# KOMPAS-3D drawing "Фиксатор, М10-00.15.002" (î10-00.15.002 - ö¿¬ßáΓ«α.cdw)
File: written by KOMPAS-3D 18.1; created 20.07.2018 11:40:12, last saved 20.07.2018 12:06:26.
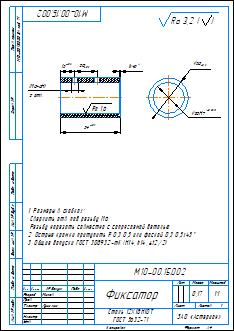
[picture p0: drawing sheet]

Sheet 1: A4, portrait

Document properties: Полное имя файла: D:\Magna\Магна Ins\Магна ins 10\М10-00.00.000\3Д\М10-00.15.002 - Фиксатор.cdw; Масса: 0.168272

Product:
- Part/product: Фиксатор  | designation М10-00.15.002
    Масса: 0.168272
    Раздел спецификации: Детали
    Форматы листов документа: A4
    source file: М10-00.15.002 - Фиксатор.cdw

Title block, sheet 1: Наименование: Фиксатор; designation: М10-00.15.002; Масса: 0,17; scale: 1:1; Количество листов документа: 1; organisation: ЗАО «Астерион»; Форматы листов документа: A4; stored path: Z:\Магна\Магна Ins\Магна ins 10\М10-00.00.000\3Д\М10-00.15.002 - Фиксатор.cdw; Разработал: Милов; Т. контр.: Лучихин

Views: Вид 1, Местный разрез 1, Вид:1, Проекционный вид 2
Referenced files in Z:\Магна\Магна Ins\Магна ins 10\М10-00.00.000\3Д\: М10-00.15.002 - Фиксатор.m3d
Referenced files in D:\Magna\Магна Ins\Магна ins 10\М10-00.00.000\3Д\: М10-00.15.002 - Фиксатор.m3d
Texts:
  Сталь 12Х18Н10Т
  ГОСТ 5632-71
  Ra 1,6
  Ra 3,2
  Ra 3,2 ( )
  М10-00.15.000 дв. габ 71
Dimensions and other numbers on the sheet: 13; 20; -6Н); 6; 2 отв.; 1; 54; 3; 28; 36; 1:1; 0,17

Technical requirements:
  Размеры в скобках:
  Сверлить отв. под резьбу М6.
  Резьбу нарезать совместно с сопрягаемой деталью.
  Острые кромки притупить R 0,3...0,5 или фаской 0,3...0,5х45 .
  Общие допуски ГОСТ 30893.2-mK (H14, h14,  t2/2).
